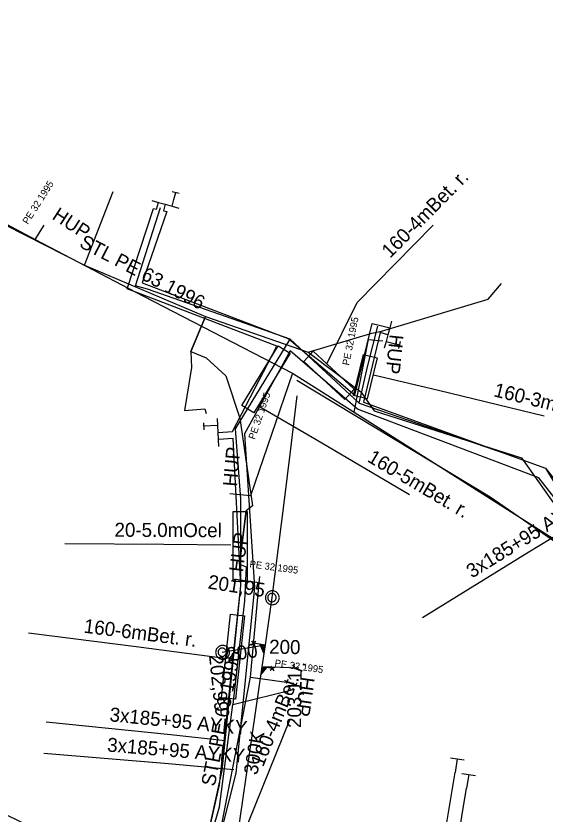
# Model space of a CAD drawing. Extents: x -746464 to -745690, y -1051581 to -1049993.
# Drawn here: x -746423.8 to -746386, y -1051012.9 to -1050955.9 of the extents above; entities that cross this region are included whole.
import ezdxf

# ---------------------------------------------------------------- set-up
doc = ezdxf.new("R2010")
doc.units = 0
for name, color, linetype in [('04_CETIN_sdelovaci_podzem', 7, 'Continuous'), ('48_Prazs_plynarenska_STL', 7, 'Continuous'), ('48_Prazs_plynarenska_STL_popisy', 7, 'Continuous'), ('51_PVaK_kanal_jednotna_neoverena poloha_pripojka', 7, 'Continuous'), ('51_PVaK_kanal_jednotna_overena poloha_rad', 7, 'Continuous'), ('51_PVaK_kanal_objekty', 7, 'Continuous'), ('51_PVaK_kanal_popisy', 7, 'Continuous'), ('51_PVaK_vodovod_overena poloha_rad', 7, 'Continuous'), ('55_PREdi_chranicky', 7, 'Continuous'), ('55_PREdi_NN', 7, 'Continuous'), ('55_PREdi_NN_popisy', 7, 'Continuous'), ('55_PREdi_NN_pripojovaci_misto', 7, 'Continuous'), ('55_PREdi_stavby_popisy', 7, 'Continuous')]:
    doc.layers.add(name, color=color, linetype=linetype)

msp = doc.modelspace()

# ---------------------------------------------------------------- linework, layer by layer
at = {"layer": '04_CETIN_sdelovaci_podzem'}
for points in [[(-746436.71, -1050967.48), (-746430.4, -1050971.31), (-746428.85, -1050968.68), (-746418.92, -1050973.73)], [(-746418.92, -1050973.73), (-746416.86, -1050968.46)], [(-746418.92, -1050973.73), (-746410.27, -1050977.4)], [(-746397.7, -1050978.44), (-746390.09, -1050976.15), (-746389.14, -1050975.04)], [(-746411.33, -1050979.88), (-746410.27, -1050977.4)], [(-746410.27, -1050977.4), (-746411.33, -1050979.88)], [(-746410.27, -1050977.4), (-746402.94, -1050979.94)], [(-746402.94, -1050979.94), (-746398.39, -1050978.58), (-746397.7, -1050978.44)], [(-746411.33, -1050979.88), (-746410.22, -1050980.34), (-746408.82, -1050981.63), (-746407.83, -1050984.66), (-746406.91, -1050990.91)], [(-746411.33, -1050979.88), (-746411.28, -1050981.04)], [(-746402.94, -1050979.94), (-746399.18, -1050982.77), (-746398.22, -1050984.12), (-746387.71, -1050987.47), (-746384.48, -1050992.05), (-746381.76, -1050994.97), (-746371, -1050998.36), (-746370.7, -1050998.02), (-746370.5, -1050987.87)], [(-746411.28, -1050981.04), (-746411.76, -1050984.11), (-746410.31, -1050983.99), (-746410.23, -1050984.31)], [(-746406.91, -1050990.91), (-746407.38, -1050991.26), (-746407.84, -1050995.07), (-746407.36, -1050995.27), (-746407.5, -1050997.7), (-746408.32, -1051005.09)], [(-746407.84, -1050995.07), (-746407.38, -1050991.26)], [(-746408.32, -1051005.09), (-746403.93, -1051003.99)], [(-746408.32, -1051005.09), (-746403.93, -1051003.99)], [(-746410.72, -1051017.45), (-746409.28, -1051012.4), (-746408.32, -1051005.09)]]:
    msp.add_lwpolyline(points, dxfattribs=at)
at = {"layer": '48_Prazs_plynarenska_STL'}
for points in [[(-746458.107, -1050955.931), (-746454.15, -1050957.41), (-746445.22, -1050960.98), (-746435.81, -1050964.74), (-746422.44, -1050971.9), (-746414.71, -1050975.94), (-746404.06, -1050981.43), (-746399.66, -1050984.21), (-746380.77, -1050996.22), (-746365.51, -1051001.19), (-746365.059, -1051001.349)], [(-746422.44, -1050971.9), (-746421.79, -1050970.88)], [(-746399.66, -1050984.21), (-746398.63, -1050979.03), (-746397.618, -1050979.137)], [(-746404.06, -1050981.43), (-746407.06, -1050990.19), (-746408.529, -1050990.059)], [(-746411.209, -1051026.506), (-746409.74, -1051016.95), (-746407.07, -1051003.13), (-746406.45, -1050996.4), (-746406.4, -1050995.95)], [(-746406.45, -1050996.4), (-746408.108, -1050996.179)], [(-746407.07, -1051003.13), (-746403.958, -1051003.578)]]:
    msp.add_lwpolyline(points, dxfattribs=at)
at = {"layer": '51_PVaK_kanal_jednotna_neoverena poloha_pripojka'}
for p, q in [((-746409.08, -1051001.36), (-746406.021, -1051000.828)), ((-746403.6, -1051002.5), (-746406.251, -1051002.412))]:
    msp.add_line(p, q, dxfattribs=at)
at = {"layer": '51_PVaK_kanal_jednotna_overena poloha_rad'}
for points in [[(-746403.74, -1050983.05), (-746404.236, -1050987.04), (-746404.667, -1050990.513), (-746405.53, -1050997.46)], [(-746405.53, -1050997.46), (-746406.021, -1051000.828), (-746406.251, -1051002.412), (-746408.76, -1051019.63)]]:
    msp.add_lwpolyline(points, dxfattribs=at)
at = {"layer": '51_PVaK_kanal_objekty'}
for p, q in [((-746406.725, -1051000.875), (-746406.975, -1051000.541)), ((-746407.022, -1051000.823), (-746406.685, -1051000.571)), ((-746405.653, -1051002.651), (-746405.332, -1051002.413)), ((-746405.367, -1051002.681), (-746405.608, -1051002.367))]:
    msp.add_line(p, q, dxfattribs=at)
for points in [[(-746405, -1050997.47), (-746405.01, -1050997.42), (-746405.01, -1050997.37), (-746405.03, -1050997.32), (-746405.05, -1050997.27), (-746405.07, -1050997.22), (-746405.1, -1050997.18), (-746405.13, -1050997.14), (-746405.17, -1050997.1), (-746405.21, -1050997.07), (-746405.25, -1050997.04), (-746405.3, -1050997.02), (-746405.35, -1050997), (-746405.4, -1050996.98), (-746405.45, -1050996.98), (-746405.5, -1050996.97), (-746405.55, -1050996.98), (-746405.6, -1050996.98), (-746405.65, -1050997), (-746405.7, -1050997.02), (-746405.75, -1050997.04), (-746405.79, -1050997.07), (-746405.83, -1050997.1), (-746405.87, -1050997.14), (-746405.9, -1050997.18), (-746405.93, -1050997.22), (-746405.95, -1050997.27), (-746405.97, -1050997.32), (-746405.99, -1050997.37), (-746405.99, -1050997.42), (-746406, -1050997.47), (-746405.99, -1050997.52), (-746405.99, -1050997.57), (-746405.97, -1050997.62), (-746405.95, -1050997.67), (-746405.93, -1050997.72), (-746405.9, -1050997.76), (-746405.87, -1050997.8), (-746405.83, -1050997.84), (-746405.79, -1050997.87), (-746405.75, -1050997.9), (-746405.7, -1050997.92), (-746405.65, -1050997.94), (-746405.6, -1050997.96), (-746405.55, -1050997.96), (-746405.5, -1050997.97), (-746405.45, -1050997.96), (-746405.4, -1050997.96), (-746405.35, -1050997.94), (-746405.3, -1050997.92), (-746405.25, -1050997.9), (-746405.21, -1050997.87), (-746405.17, -1050997.84), (-746405.13, -1050997.8), (-746405.1, -1050997.76), (-746405.07, -1050997.72), (-746405.05, -1050997.67), (-746405.03, -1050997.62), (-746405.01, -1050997.57), (-746405.01, -1050997.52), (-746405, -1050997.47)], [(-746405.23, -1050997.46), (-746405.23, -1050997.43), (-746405.236, -1050997.4), (-746405.242, -1050997.37), (-746405.254, -1050997.34), (-746405.272, -1050997.31), (-746405.29, -1050997.286), (-746405.308, -1050997.262), (-746405.332, -1050997.238), (-746405.356, -1050997.22), (-746405.38, -1050997.202), (-746405.41, -1050997.184), (-746405.44, -1050997.172), (-746405.47, -1050997.166), (-746405.5, -1050997.16), (-746405.53, -1050997.16), (-746405.56, -1050997.16), (-746405.59, -1050997.166), (-746405.62, -1050997.172), (-746405.65, -1050997.184), (-746405.68, -1050997.202), (-746405.704, -1050997.22), (-746405.728, -1050997.238), (-746405.752, -1050997.262), (-746405.77, -1050997.286), (-746405.788, -1050997.31), (-746405.806, -1050997.34), (-746405.818, -1050997.37), (-746405.824, -1050997.4), (-746405.83, -1050997.43), (-746405.83, -1050997.46), (-746405.83, -1050997.49), (-746405.824, -1050997.52), (-746405.818, -1050997.55), (-746405.806, -1050997.58), (-746405.788, -1050997.61), (-746405.77, -1050997.634), (-746405.752, -1050997.658), (-746405.728, -1050997.682), (-746405.704, -1050997.7), (-746405.68, -1050997.718), (-746405.65, -1050997.736), (-746405.62, -1050997.748), (-746405.59, -1050997.754), (-746405.56, -1050997.76), (-746405.53, -1050997.76), (-746405.5, -1050997.76), (-746405.47, -1050997.754), (-746405.44, -1050997.748), (-746405.41, -1050997.736), (-746405.38, -1050997.718), (-746405.356, -1050997.7), (-746405.332, -1050997.682), (-746405.308, -1050997.658), (-746405.29, -1050997.634), (-746405.272, -1050997.61), (-746405.254, -1050997.58), (-746405.242, -1050997.55), (-746405.236, -1050997.52), (-746405.23, -1050997.49), (-746405.23, -1050997.46)], [(-746408.55, -1051001.37), (-746408.56, -1051001.32), (-746408.56, -1051001.27), (-746408.58, -1051001.22), (-746408.6, -1051001.17), (-746408.62, -1051001.12), (-746408.65, -1051001.08), (-746408.68, -1051001.04), (-746408.72, -1051001), (-746408.76, -1051000.97), (-746408.8, -1051000.94), (-746408.85, -1051000.92), (-746408.9, -1051000.9), (-746408.95, -1051000.88), (-746409, -1051000.88), (-746409.05, -1051000.87), (-746409.1, -1051000.88), (-746409.15, -1051000.88), (-746409.2, -1051000.9), (-746409.25, -1051000.92), (-746409.3, -1051000.94), (-746409.34, -1051000.97), (-746409.38, -1051001), (-746409.42, -1051001.04), (-746409.45, -1051001.08), (-746409.48, -1051001.12), (-746409.5, -1051001.17), (-746409.52, -1051001.22), (-746409.54, -1051001.27), (-746409.54, -1051001.32), (-746409.55, -1051001.37), (-746409.54, -1051001.42), (-746409.54, -1051001.47), (-746409.52, -1051001.52), (-746409.5, -1051001.57), (-746409.48, -1051001.62), (-746409.45, -1051001.66), (-746409.42, -1051001.7), (-746409.38, -1051001.74), (-746409.34, -1051001.77), (-746409.3, -1051001.8), (-746409.25, -1051001.82), (-746409.2, -1051001.84), (-746409.15, -1051001.86), (-746409.1, -1051001.86), (-746409.05, -1051001.87), (-746409, -1051001.86), (-746408.95, -1051001.86), (-746408.9, -1051001.84), (-746408.85, -1051001.82), (-746408.8, -1051001.8), (-746408.76, -1051001.77), (-746408.72, -1051001.74), (-746408.68, -1051001.7), (-746408.65, -1051001.66), (-746408.62, -1051001.62), (-746408.6, -1051001.57), (-746408.58, -1051001.52), (-746408.56, -1051001.47), (-746408.56, -1051001.42), (-746408.55, -1051001.37)], [(-746408.78, -1051001.36), (-746408.78, -1051001.33), (-746408.786, -1051001.3), (-746408.792, -1051001.27), (-746408.804, -1051001.24), (-746408.822, -1051001.21), (-746408.84, -1051001.186), (-746408.858, -1051001.162), (-746408.882, -1051001.138), (-746408.906, -1051001.12), (-746408.93, -1051001.102), (-746408.96, -1051001.084), (-746408.99, -1051001.072), (-746409.02, -1051001.066), (-746409.05, -1051001.06), (-746409.08, -1051001.06), (-746409.11, -1051001.06), (-746409.14, -1051001.066), (-746409.17, -1051001.072), (-746409.2, -1051001.084), (-746409.23, -1051001.102), (-746409.254, -1051001.12), (-746409.278, -1051001.138), (-746409.302, -1051001.162), (-746409.32, -1051001.186), (-746409.338, -1051001.21), (-746409.356, -1051001.24), (-746409.368, -1051001.27), (-746409.374, -1051001.3), (-746409.38, -1051001.33), (-746409.38, -1051001.36), (-746409.38, -1051001.39), (-746409.374, -1051001.42), (-746409.368, -1051001.45), (-746409.356, -1051001.48), (-746409.338, -1051001.51), (-746409.32, -1051001.534), (-746409.302, -1051001.558), (-746409.278, -1051001.582), (-746409.254, -1051001.6), (-746409.23, -1051001.618), (-746409.2, -1051001.636), (-746409.17, -1051001.648), (-746409.14, -1051001.654), (-746409.11, -1051001.66), (-746409.08, -1051001.66), (-746409.05, -1051001.66), (-746409.02, -1051001.654), (-746408.99, -1051001.648), (-746408.96, -1051001.636), (-746408.93, -1051001.618), (-746408.906, -1051001.6), (-746408.882, -1051001.582), (-746408.858, -1051001.558), (-746408.84, -1051001.534), (-746408.822, -1051001.51), (-746408.804, -1051001.48), (-746408.792, -1051001.45), (-746408.786, -1051001.42), (-746408.78, -1051001.39), (-746408.78, -1051001.36)], [(-746406.856, -1051000.701), (-746406.022, -1051000.823), (-746406.109, -1051001.418), (-746406.398, -1051000.768)], [(-746406.321, -1051000.824), (-746406.078, -1051000.859), (-746406.134, -1051001.239), (-746406.321, -1051000.82)], [(-746406.24, -1051000.88), (-746406.119, -1051000.898), (-746406.147, -1051001.093), (-746406.239, -1051000.876)], [(-746405.466, -1051002.523), (-746406.251, -1051002.409), (-746406.332, -1051002.969), (-746405.897, -1051002.461)], [(-746405.981, -1051002.491), (-746406.21, -1051002.457), (-746406.262, -1051002.815), (-746405.981, -1051002.487)], [(-746406.07, -1051002.52), (-746406.184, -1051002.503), (-746406.211, -1051002.687), (-746406.069, -1051002.516)]]:
    msp.add_lwpolyline(points, dxfattribs=at)
at = {"layer": '51_PVaK_vodovod_overena poloha_rad'}
msp.add_lwpolyline([(-746403.74, -1050981.93), (-746389.96, -1050990.26), (-746387.95, -1050991.64), (-746380.97, -1050996.46), (-746366.125, -1051001.295), (-746365.651, -1051001.45)], dxfattribs=at)
at = {"layer": '55_PREdi_chranicky'}
for points in [[(-746405.084, -1050979.479), (-746404.23, -1050979.999), (-746406.829, -1050984.271), (-746407.683, -1050983.751), (-746405.084, -1050979.479)], [(-746399.648, -1050982.588), (-746400.33, -1050983.319), (-746403.256, -1050980.593), (-746402.574, -1050979.862), (-746399.648, -1050982.588)], [(-746398.726, -1050983.262), (-746399.697, -1050983.026), (-746398.989, -1050980.111), (-746398.018, -1050980.347), (-746398.726, -1050983.262)], [(-746408.297, -1050991.322), (-746407.297, -1050991.321), (-746407.293, -1050996.321), (-746408.293, -1050996.322), (-746408.297, -1050991.322)], [(-746408.487, -1050998.65), (-746407.492, -1050998.754), (-746408.133, -1051004.72), (-746409.128, -1051004.616), (-746408.487, -1050998.65)]]:
    msp.add_lwpolyline(points, close=True, dxfattribs=at)
at = {"layer": '55_PREdi_NN'}
for points in [[(-746414.109, -1050969.106), (-746413.627, -1050969.24), (-746413.145, -1050969.374), (-746412.663, -1050969.508), (-746412.182, -1050969.643)], [(-746412.663, -1050969.508), (-746412.529, -1050969.027)], [(-746409.374, -1050985.662), (-746408.334, -1050985.607), (-746405.181, -1050979.506), (-746415.87, -1050975.411), (-746413.987, -1050969.668), (-746413.76, -1050969.718), (-746413.627, -1050969.24)], [(-746404.228, -1050978.997), (-746414.412, -1050975.443), (-746415.26, -1050975.209), (-746413.475, -1050969.609)], [(-746413.145, -1050969.374), (-746413.278, -1050969.852), (-746413.045, -1050969.903), (-746414.787, -1050974.988), (-746404.333, -1050978.988), (-746399.601, -1050983.001), (-746398.376, -1050977.893), (-746397.683, -1050978.059), (-746397.123, -1050978.207)], [(-746396.996, -1050977.723), (-746397.123, -1050978.207), (-746397.251, -1050978.69), (-746397.378, -1050979.174), (-746397.506, -1050979.657)], [(-746399.302, -1050983.578), (-746398.678, -1050980.883), (-746397.961, -1050978.072)], [(-746397.251, -1050978.69), (-746397.811, -1050978.543), (-746398.988, -1050983.496), (-746385.989, -1050988.229), (-746384.666, -1050989.903), (-746383.849, -1050989.367)], [(-746410.997, -1051017.845), (-746410.472, -1051016.082), (-746409.284, -1051010.839), (-746407.756, -1050996.625), (-746407.751, -1050990.419), (-746408.14, -1050985.416), (-746404.228, -1050978.997)], [(-746404.228, -1050978.997), (-746399.302, -1050983.578)], [(-746397.378, -1050979.174), (-746396.895, -1050979.301)], [(-746384.218, -1050991.777), (-746386.486, -1050988.899), (-746399.412, -1050984.014), (-746404.239, -1050979.835), (-746407.489, -1050985.767), (-746406.782, -1050996.737), (-746408.102, -1051009.995), (-746409.631, -1051016.029), (-746410.244, -1051018.195), (-746405.515, -1051019.874), (-746400.986, -1051019.255), (-746392.392, -1051021.23), (-746391.631, -1051017.155)], [(-746399.302, -1050983.578), (-746388.953, -1050987.147), (-746385.989, -1050988.229), (-746384.135, -1050991.286), (-746383.667, -1050992.074), (-746383.519, -1050992.323), (-746382.964, -1050991.998)], [(-746409.401, -1050985.163), (-746409.9, -1050985.189)], [(-746409.321, -1050986.661), (-746409.348, -1050986.162), (-746409.374, -1050985.662), (-746409.401, -1050985.163), (-746409.427, -1050984.664)], [(-746428.573, -1051010.988), (-746422.853, -1051013.746), (-746410.997, -1051017.845), (-746410.472, -1051016.082), (-746409.087, -1051009.798), (-746407.756, -1050996.625), (-746408.308, -1050986.107), (-746409.348, -1050986.162)], [(-746393.601, -1051016.813), (-746392.456, -1051009.946)], [(-746392.616, -1051016.984), (-746391.629, -1051011.069)]]:
    msp.add_lwpolyline(points, dxfattribs=at)
at = {"layer": '55_PREdi_NN_popisy'}
for points in [[(-746394.791, -1050998.878), (-746387.188, -1050994.182), (-746384.055, -1050992.288)], [(-746421.648, -1051006.335), (-746412.757, -1051007.231), (-746408.858, -1051007.659)], [(-746421.816, -1051008.579), (-746412.91, -1051009.315), (-746408.24, -1051009.735)]]:
    msp.add_lwpolyline(points, dxfattribs=at)
at = {"layer": '55_PREdi_NN_pripojovaci_misto'}
for p, q in [((-746412.158, -1050968.609), (-746412.641, -1050968.479)), ((-746412.529, -1050969.027), (-746412.4, -1050968.544)), ((-746396.895, -1050979.301), (-746396.41, -1050979.422)), ((-746396.47, -1050979.665), (-746396.349, -1050979.179)), ((-746410.416, -1050984.974), (-746410.381, -1050985.473)), ((-746409.9, -1050985.189), (-746410.399, -1050985.224)), ((-746392.79, -1051008.891), (-746391.812, -1051009.046)), ((-746392.301, -1051008.968), (-746392.456, -1051009.946)), ((-746391.963, -1051010.014), (-746390.985, -1051010.169)), ((-746391.474, -1051010.091), (-746391.629, -1051011.069))]:
    msp.add_line(p, q, dxfattribs=at)
at = {"layer": '55_PREdi_stavby_popisy'}
for points in [[(-746401.619, -1050980.76), (-746399.456, -1050976.386), (-746394.013, -1050970.863)], [(-746398.287, -1050981.545), (-746393.636, -1050982.645), (-746386.103, -1050984.486)], [(-746406.547, -1050983.743), (-746402.378, -1050986.165), (-746395.7, -1050990.108)], [(-746420.304, -1050993.6), (-746413.236, -1050993.634), (-746408.465, -1050993.691)], [(-746422.91, -1050999.965), (-746415.217, -1051000.949), (-746408.886, -1051001.794)], [(-746408.76, -1051018.09), (-746407.164, -1051013.383), (-746404.24, -1051006.2)]]:
    msp.add_lwpolyline(points, dxfattribs=at)

# ---------------------------------------------------------------- texts
at = {"layer": '48_Prazs_plynarenska_STL_popisy'}
for s, height, rotation, p in [('PE 32 1995', 0.5, 57.4925, (-746422.957, -1050970.85)), ('HUP', 1, 327, (-746421.29, -1050970.38)), ('STL PE 63 1996', 1, 332.4067, (-746419.349, -1050972.387)), ('PE 32 1995', 0.5, 78.7539, (-746400.023, -1050980.91)), ('HUP', 1, 264, (-746397.118, -1050978.637)), ('PE 32 1995', 0.5, 71.0954, (-746406.754, -1050986.209)), ('HUP', 1, 85, (-746408.029, -1050989.559)), ('HUP', 1, 82, (-746407.608, -1050995.679)), ('PE 32 1995', 0.5, 352.4076, (-746407.151, -1050995.298)), ('STL PE 63 1995', 1, 79.0653, (-746409.605, -1051010.98)), ('PE 32 1995', 0.5, 351.808, (-746405.364, -1051002.365)), ('HUP', 1, 262, (-746403.458, -1051003.078))]:
    msp.add_text(s, height=height, rotation=rotation, dxfattribs=at).set_placement(p)
at = {"layer": '51_PVaK_kanal_popisy'}
for s, rotation, p in [('201,95', 351.2222, (-746410.146, -1050996.806)), ('200', 359.0991, (-746405.731, -1051001.465)), ('200', 8.865, (-746408.695, -1051002.039)), ('202,99', 275.9091, (-746410.025, -1051001.585)), ('203,11', 89.2371, (-746403.451, -1051006.772)), ('300K', 80.709, (-746406.564, -1051010.163))]:
    msp.add_text(s, height=1, rotation=rotation, dxfattribs=at).set_placement(p)
at = {"layer": '55_PREdi_NN_popisy'}
for rotation, p in [(31.6978, (-746391.253, -1050996.105)), (354.242, (-746417.152, -1051006.286)), (355.2765, (-746417.322, -1051008.449))]:
    msp.add_text('3x185+95 AYKY', height=1, rotation=rotation, dxfattribs=at).set_placement(p)
at = {"layer": '55_PREdi_stavby_popisy'}
for s, rotation, p in [('160-4mBet. r.', 45.4189, (-746397.09, -1050973.274)), ('160-3mBet. r.', 346.2743, (-746389.751, -1050983.079)), ('160-5mBet. r.', 329.4364, (-746398.785, -1050987.706)), ('20-5.0mOcel', 359.729, (-746416.768, -1050993.117)), ('160-6mBet. r.', 352.7085, (-746419, -1050999.961)), ('160-4mBet. r.', 67.8501, (-746406.165, -1051009.602))]:
    msp.add_text(s, height=1, rotation=rotation, dxfattribs=at).set_placement(p)

doc.saveas('drawing.dxf')
